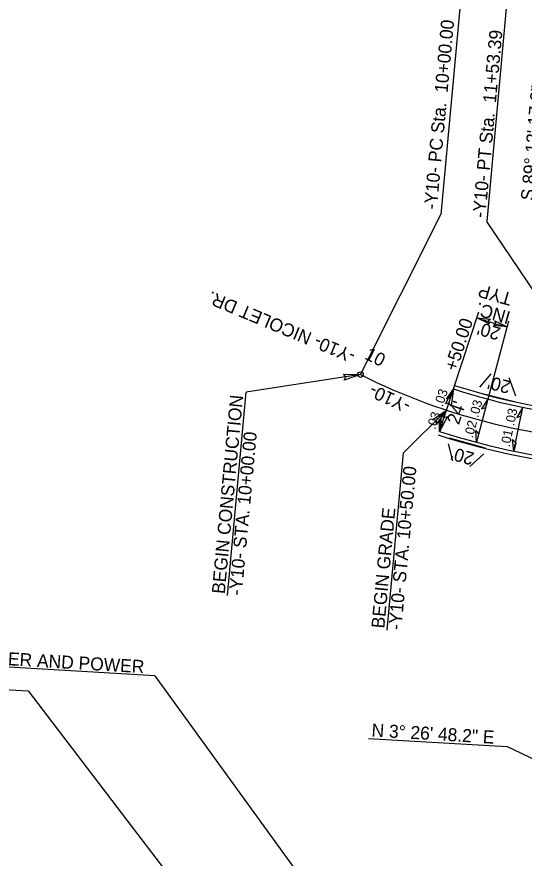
# Model space of a CAD drawing. Extents: x 2010838 to 2015151, y 441905 to 447792.
# Drawn here: x 2011691.7 to 2011964.2, y 445190.9 to 445642.5 of the extents above; entities that cross this region are included whole.
import ezdxf

# ---------------------------------------------------------------- set-up
doc = ezdxf.new("R2010")
doc.units = 0
for name, color, linetype in [('A-Wall-Blow', 7, 'Continuous'), ('A-Wall-Comp', 7, 'Continuous'), ('C-EOP 1', 7, 'Continuous'), ('C-Grave Plots', 7, 'Continuous'), ('CLRD', 7, 'Continuous'), ('Cont-2-Lidar', 7, 'Continuous'), ('Default_10ft_LIDAR_Contou', 7, 'Continuous'), ('Default_2FT_LIDAR_Contour', 7, 'Continuous'), ('s-Existing Major', 7, 'Continuous'), ('S-Existing Minor', 7, 'Continuous'), ('S-overhead electric', 7, 'Continuous'), ('TEXT-LG', 7, 'Continuous'), ('TEXT-MED', 7, 'Continuous'), ('X2', 7, 'Continuous')]:
    doc.layers.add(name, color=color, linetype=linetype)

msp = doc.modelspace()

# ---------------------------------------------------------------- linework, layer by layer
at = {"layer": 'A-Wall-Blow'}
for p, q in [((2011922.45, 445431.43), (2011926.21, 445442.83)), ((2011944.7, 445437.33), (2011938.54, 445414.14)), ((2011918.7, 445420.03), (2011922.45, 445431.43)), ((2011958.7, 445409.42), (2011963.48, 445432.94))]:
    msp.add_line(p, q, dxfattribs=at)
at = {"layer": 'A-Wall-Comp'}
for points in [[(2011926.21, 445442.83), (2011922.43, 445437.75), (2011924.76, 445438.43)], [(2011944.7, 445437.33), (2011941.23, 445432.05), (2011943.51, 445432.86)], [(2011963.48, 445432.94), (2011960.33, 445427.46), (2011962.56, 445428.41)], [(2011918.7, 445420.03), (2011918.68, 445426.36), (2011920.14, 445424.42)], [(2011938.54, 445414.14), (2011938.15, 445420.45), (2011939.73, 445418.61)], [(2011958.7, 445409.42), (2011957.94, 445415.7), (2011959.62, 445413.95)]]:
    msp.add_lwpolyline(points, close=True, dxfattribs=at)
at = {"layer": 'C-EOP 1'}
msp.add_line((2011876.28, 445450.5), (2011879.87, 445457.65), dxfattribs=at)
at = {"layer": 'CLRD'}
msp.add_arc((2012028.74, 445754.16), 339.78, 243.3399, 269.2048, dxfattribs=at)
msp.add_arc((2012028.74, 445754.16), 339.78, 243.3399, 269.2048, dxfattribs=at)
at = {"layer": 'Default_10ft_LIDAR_Contou'}
for p, q in [((2011929.91, 445650.86), (2011919.38, 445536.35)), ((2011954.58, 445647.23), (2011944.05, 445532.71)), ((2011876.28, 445450.5), (2011919.38, 445536.35)), ((2012024.02, 445414.41), (2011944.05, 445532.71)), ((2011572.45, 445288.09), (2011697.89, 445280.7)), ((2011697.89, 445280.7), (2011917.77, 444992.65)), ((2011880.58, 445255.21), (2011954.92, 445250.82)), ((2012052.87, 445203.91), (2011954.92, 445250.82))]:
    msp.add_line(p, q, dxfattribs=at)
msp.add_circle((2011876.28, 445450.5), 1.5, dxfattribs=at)
at = {"layer": 's-Existing Major'}
for points in [[(2011945.33, 445477.76), (2011938.76, 445480.95), (2011946.07, 445480.17), (2011944.83, 445479.2)], [(2011948.42, 445479.32), (2011954.99, 445476.13), (2011947.68, 445476.91), (2011948.92, 445477.89)], [(2011867.15, 445450.67), (2011876.28, 445450.5), (2011867.58, 445447.55), (2011868.47, 445449.3)], [(2011921.92, 445434.76), (2011926.21, 445442.83), (2011924.89, 445433.73), (2011923.73, 445435.32)], [(2011914.97, 445426.19), (2011922.45, 445431.43), (2011917.15, 445423.92), (2011916.84, 445425.87)], [(2011922.99, 445428.09), (2011918.7, 445420.03), (2011920.01, 445429.13), (2011921.17, 445427.53)]]:
    msp.add_lwpolyline(points, close=True, dxfattribs=at)
at = {"layer": 'S-Existing Minor'}
for p, q in [((2011926.21, 445442.83), (2011939.85, 445484.26)), ((2011955.78, 445479.1), (2011944.7, 445437.33)), ((2011876.28, 445450.5), (2011814.92, 445441.07)), ((2011804.88, 445331.86), (2011814.92, 445441.07)), ((2011918.7, 445420.03), (2011926.21, 445442.83)), ((2011922.45, 445431.43), (2011899.32, 445408.49)), ((2011890.57, 445313.36), (2011899.32, 445408.49)), ((2011765.91, 445288.76), (2011572.29, 445300.18)), ((2011765.91, 445288.76), (2011921.98, 445073.52))]:
    msp.add_line(p, q, dxfattribs=at)
msp.add_arc((2012028.74, 445754.16), 287.64, 251.7712, 255.1438, dxfattribs=at)
at = {"layer": 'S-overhead electric'}
for p, q in [((2011940.37, 445443.82), (2011946.47, 445450.87)), ((2011959.77, 445438.94), (2011956.06, 445448.68)), ((2011923.3, 445413.42), (2011925.61, 445404.29)), ((2011942.57, 445408.04), (2011935.03, 445401.14))]:
    msp.add_line(p, q, dxfattribs=at)
for radius, end in [(327.78, 266.0644), (351.78, 266.1604)]:
    msp.add_arc((2012028.74, 445754.16), radius, 251.7712, end, dxfattribs=at)
at = {"layer": 'TEXT-LG'}
msp.add_arc((2011877.67, 445201.69), 128.5, 309.2044, 356.5533, dxfattribs=at)
at = {"layer": 'TEXT-MED'}
for radius, end in [(325.78, 266.0644), (353.78, 266.1604)]:
    msp.add_arc((2012028.74, 445754.16), radius, 251.7712, end, dxfattribs=at)
at = {"layer": 'X2'}
for p, q in [((2011939.64, 445440.91), (2011959.04, 445436.03)), ((2011943.37, 445410.93), (2011924.11, 445416.31))]:
    msp.add_line(p, q, dxfattribs=at)

# ---------------------------------------------------------------- texts
at = {"layer": 'A-Wall-Blow'}
for s, rotation, p in [('.03', 71.7712, (2011920.41, 445432.92)), ('.03', 75.1438, (2011939.45, 445427.16)), ('.03', 78.5163, (2011958.75, 445422.72)), ('.03', 71.7712, (2011916.44, 445420.73)), ('.02', 75.1438, (2011936.57, 445416.15)), ('.01', 78.5163, (2011956.37, 445411.41))]:
    msp.add_text(s, height=5, rotation=rotation, dxfattribs=at).set_placement(p)
at = {"layer": 'C-Grave Plots'}
for s, rotation, p in [('-Y10- NICOLET DR.', 157.4014, (2011874.22, 445462.94)), ('TYP', 163.8791, (2011958.25, 445494.08)), ('INC. ', 163.8791, (2011957.35, 445484.13)), ('+50.00', 71.7712, (2011927.8, 445451.87)), ("20'", 163.8791, (2011952, 445475.48)), ("20'", 165.6768, (2011957.5, 445446.86)), ('BEGIN CONSTRUCTION', 84.6754, (2011803.36, 445332.57)), ("24'", 71.7712, (2011929.12, 445423.24)), ('-Y10- STA. 10+00.00', 84.6754, (2011812.5, 445331.71)), ("20'", 164.4078, (2011937.82, 445408.43)), ('-Y10- STA. 10+50.00', 84.6754, (2011898.19, 445313.21)), ('BEGIN GRADE', 84.6754, (2011889.05, 445314.07))]:
    msp.add_text(s, height=7, rotation=rotation, dxfattribs=at).set_placement(p)
at = {"layer": 'Cont-2-Lidar'}
for s, rotation, p in [('S 89%%d 12\' 17.2" E', 84.7467, (2011969.31, 445543.7)), ('N 3%%d 26\' 48.2" E', 356.6264, (2011882.07, 445256.24))]:
    msp.add_text(s, height=7, rotation=rotation, dxfattribs=at).set_placement(p)
at = {"layer": 'Default_10ft_LIDAR_Contou'}
for s, p in [('-Y10- PC Sta.  10+00.00', (2011917.26, 445538.85)), ('-Y10- PT Sta.  11+53.39', (2011943.32, 445534.41))]:
    msp.add_text(s, height=7, rotation=84.7467, dxfattribs=at).set_placement(p)
at = {"layer": 'Default_2FT_LIDAR_Contour'}
for s, rotation, p in [('10', 333.3399, (2011878.04, 445459.18)), ('-Y10-', 155.1352, (2011903.8, 445435.9))]:
    msp.add_text(s, height=7, rotation=rotation, dxfattribs=at).set_placement(p)
at = {"layer": 'S-Existing Minor'}
msp.add_text('2-4" CONDUITS FOR WATER AND POWER', height=7, rotation=356.6264, dxfattribs=at).set_placement((2011572.9, 445301.23))

doc.saveas('drawing.dxf')
